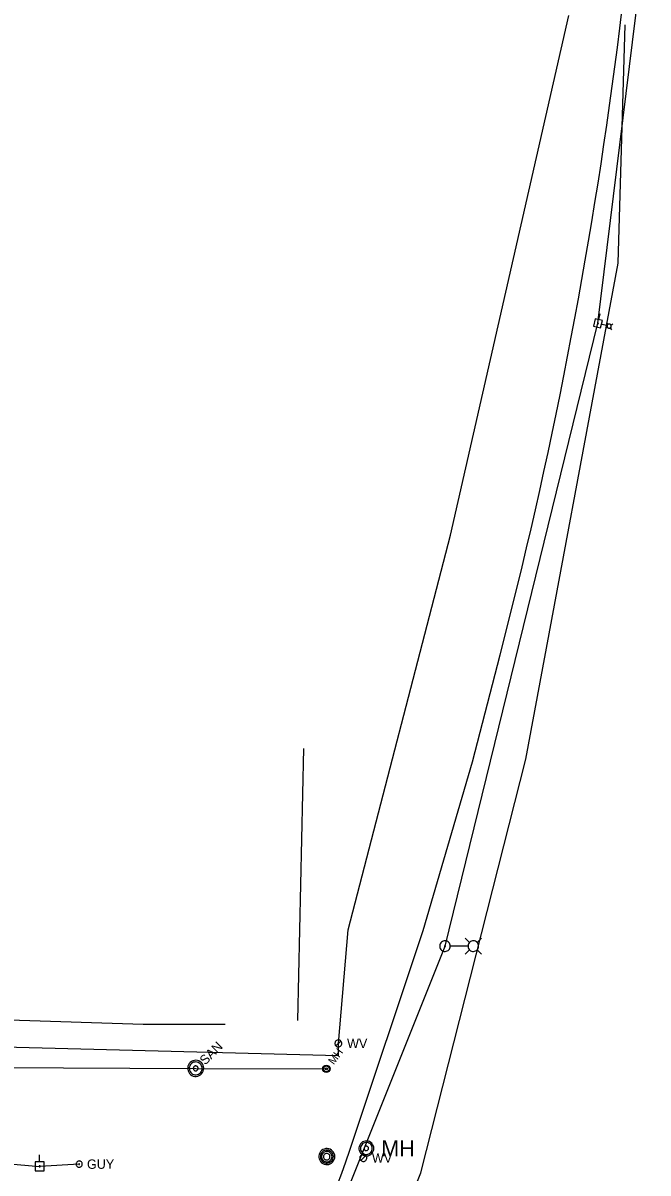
# Model space of a CAD drawing. Extents: x 600849 to 606371, y 330010 to 403088.
# Drawn here: x 604605.3 to 604861.8, y 331374.2 to 331845.6 of the extents above; entities that cross this region are included whole.
import ezdxf

# ---------------------------------------------------------------- set-up
doc = ezdxf.new("R2010")
doc.units = 0
for name, color, linetype in [('E_LTG', 7, 'Continuous'), ('E_LTG_CID', 7, 'Continuous'), ('E_UTL_EGuyWire', 7, 'Continuous'), ('E_UTL_EPowerPole', 7, 'Continuous'), ('E_UTL_G_UG', 7, 'Continuous'), ('E_UTL_MH', 7, 'Continuous'), ('E_UTL_Overhead', 7, 'Continuous'), ('E_UTL_SAN', 7, 'Continuous'), ('E_UTL_SAN_MH', 7, 'Continuous'), ('E_UTL_SAN_UG', 7, 'Continuous'), ('E_UTL_W', 7, 'Continuous'), ('E_UTL_W_MH', 7, 'Continuous'), ('E_UTL_W_UG', 7, 'Continuous')]:
    doc.layers.add(name, color=color, linetype=linetype)

msp = doc.modelspace()

# ---------------------------------------------------------------- linework, layer by layer
at = {"layer": 'E_LTG'}
for points in [[(604845.03, 331721.53), (604842.73, 331722.07)], [(604845.16, 331720.88), (604844.32, 331720.36)], [(604845.43, 331722.05), (604844.91, 331722.89)], [(604846.71, 331721.13), (604846.73, 331721.29), (604846.72, 331721.45), (604846.68, 331721.61), (604846.61, 331721.76), (604846.52, 331721.89), (604846.4, 331722), (604846.26, 331722.09), (604846.11, 331722.15), (604845.95, 331722.18), (604845.79, 331722.18), (604845.63, 331722.14), (604845.48, 331722.08), (604845.34, 331721.99), (604845.23, 331721.88), (604845.13, 331721.75), (604845.07, 331721.6), (604845.03, 331721.44), (604845.02, 331721.28), (604845.05, 331721.12), (604845.1, 331720.97), (604845.18, 331720.83), (604845.29, 331720.7), (604845.42, 331720.61), (604845.56, 331720.53), (604845.72, 331720.49), (604845.88, 331720.47), (604846.04, 331720.49), (604846.2, 331720.53), (604846.34, 331720.61), (604846.47, 331720.71), (604846.57, 331720.83), (604846.65, 331720.97), (604846.71, 331721.13)], [(604846.32, 331720.61), (604846.84, 331719.77)], [(604846.6, 331721.77), (604847.43, 331722.29)], [(604788.6, 331468.69), (604786.82, 331470.47)], [(604791.65, 331468.69), (604793.43, 331470.47)], [(604780.7, 331467.17), (604780.66, 331467.58), (604780.54, 331467.97), (604780.35, 331468.34), (604780.09, 331468.67), (604779.78, 331468.94), (604779.42, 331469.15), (604779.03, 331469.28), (604778.62, 331469.34), (604778.21, 331469.32), (604777.81, 331469.22), (604777.43, 331469.05), (604777.1, 331468.81), (604776.81, 331468.51), (604776.59, 331468.16), (604776.43, 331467.78), (604776.35, 331467.37), (604776.35, 331466.96), (604776.43, 331466.55), (604776.59, 331466.17), (604776.81, 331465.82), (604777.1, 331465.52), (604777.43, 331465.28), (604777.81, 331465.11), (604778.21, 331465.01), (604778.62, 331464.99), (604779.03, 331465.05), (604779.42, 331465.19), (604779.78, 331465.39), (604780.09, 331465.66), (604780.35, 331465.99), (604780.54, 331466.36), (604780.66, 331466.75), (604780.7, 331467.17)], [(604778.69, 331467.17), (604778.68, 331467.2), (604778.67, 331467.23), (604778.66, 331467.26), (604778.64, 331467.28), (604778.62, 331467.3), (604778.59, 331467.32), (604778.56, 331467.33), (604778.53, 331467.33), (604778.5, 331467.33), (604778.47, 331467.32), (604778.44, 331467.31), (604778.41, 331467.29), (604778.39, 331467.27), (604778.37, 331467.24), (604778.36, 331467.21), (604778.35, 331467.18), (604778.35, 331467.15), (604778.36, 331467.12), (604778.37, 331467.09), (604778.39, 331467.06), (604778.41, 331467.04), (604778.44, 331467.02), (604778.47, 331467.01), (604778.5, 331467), (604778.53, 331467), (604778.56, 331467), (604778.59, 331467.01), (604778.62, 331467.03), (604778.64, 331467.05), (604778.66, 331467.08), (604778.67, 331467.1), (604778.68, 331467.13), (604778.69, 331467.17)], [(604787.91, 331467.17), (604780.73, 331467.17)], [(604788.6, 331465.64), (604786.82, 331463.87)], [(604792.3, 331467.17), (604792.26, 331467.58), (604792.14, 331467.97), (604791.95, 331468.34), (604791.7, 331468.67), (604791.39, 331468.94), (604791.03, 331469.15), (604790.64, 331469.28), (604790.23, 331469.34), (604789.81, 331469.32), (604789.41, 331469.22), (604789.04, 331469.05), (604788.7, 331468.81), (604788.41, 331468.51), (604788.19, 331468.16), (604788.04, 331467.78), (604787.96, 331467.37), (604787.96, 331466.96), (604788.04, 331466.55), (604788.19, 331466.17), (604788.41, 331465.82), (604788.7, 331465.52), (604789.04, 331465.28), (604789.41, 331465.11), (604789.81, 331465.01), (604790.23, 331464.99), (604790.64, 331465.05), (604791.03, 331465.19), (604791.39, 331465.39), (604791.7, 331465.66), (604791.95, 331465.99), (604792.14, 331466.36), (604792.26, 331466.75), (604792.3, 331467.17)], [(604791.65, 331465.64), (604793.43, 331463.87)]]:
    msp.add_lwpolyline(points, dxfattribs=at)
at = {"layer": 'E_LTG_CID'}
msp.add_lwpolyline([(604680.92, 331223.31), (604778.52, 331467.17), (604841.28, 331722.49), (604873.72, 331985.14), (604875.05, 331997.61), (604878.05, 332072.5), (604879.01, 332133.59), (604879.29, 332193.85), (604879.03, 332249.73), (604879.6, 332255.02), (604881.21, 332520.43)], dxfattribs=at)
at = {"layer": 'E_UTL_EGuyWire'}
msp.add_line((604628.38, 331377.81), (604612.18, 331376.89), dxfattribs=at)
for points in [[(604629.67, 331377.81), (604629.64, 331378.05), (604629.57, 331378.28), (604629.46, 331378.5), (604629.31, 331378.69), (604629.13, 331378.85), (604628.92, 331378.97), (604628.69, 331379.05), (604628.44, 331379.09), (604628.2, 331379.08), (604627.96, 331379.02), (604627.74, 331378.92), (604627.54, 331378.78), (604627.37, 331378.6), (604627.24, 331378.39), (604627.15, 331378.17), (604627.11, 331377.93), (604627.11, 331377.68), (604627.15, 331377.44), (604627.24, 331377.22), (604627.37, 331377.01), (604627.54, 331376.84), (604627.74, 331376.69), (604627.96, 331376.59), (604628.2, 331376.53), (604628.44, 331376.52), (604628.69, 331376.56), (604628.92, 331376.64), (604629.13, 331376.76), (604629.31, 331376.92), (604629.46, 331377.11), (604629.57, 331377.33), (604629.64, 331377.56), (604629.67, 331377.81)], [(604628.54, 331377.81), (604628.54, 331377.84), (604628.53, 331377.86), (604628.52, 331377.89), (604628.5, 331377.92), (604628.48, 331377.94), (604628.45, 331377.95), (604628.42, 331377.96), (604628.39, 331377.97), (604628.36, 331377.96), (604628.33, 331377.96), (604628.3, 331377.94), (604628.28, 331377.93), (604628.26, 331377.9), (604628.24, 331377.88), (604628.23, 331377.85), (604628.22, 331377.82), (604628.22, 331377.79), (604628.23, 331377.76), (604628.24, 331377.73), (604628.26, 331377.71), (604628.28, 331377.68), (604628.3, 331377.67), (604628.33, 331377.65), (604628.36, 331377.65), (604628.39, 331377.65), (604628.42, 331377.65), (604628.45, 331377.66), (604628.48, 331377.67), (604628.5, 331377.69), (604628.52, 331377.72), (604628.53, 331377.75), (604628.54, 331377.77), (604628.54, 331377.81)]]:
    msp.add_lwpolyline(points, dxfattribs=at)
at = {"layer": 'E_UTL_EPowerPole'}
for points in [[(604841.61, 331723.99), (604842.17, 331726.35)], [(604840.12, 331724.35), (604839.4, 331721.35)], [(604839.4, 331721.35), (604842.39, 331720.64)], [(604843.11, 331723.64), (604840.12, 331724.35)], [(604841.47, 331722.45), (604841.48, 331722.48), (604841.48, 331722.52), (604841.47, 331722.56), (604841.45, 331722.59), (604841.43, 331722.62), (604841.4, 331722.65), (604841.37, 331722.67), (604841.34, 331722.68), (604841.3, 331722.69), (604841.26, 331722.69), (604841.22, 331722.68), (604841.19, 331722.67), (604841.16, 331722.65), (604841.13, 331722.62), (604841.11, 331722.59), (604841.09, 331722.56), (604841.08, 331722.52), (604841.08, 331722.48), (604841.09, 331722.44), (604841.1, 331722.41), (604841.12, 331722.38), (604841.14, 331722.35), (604841.17, 331722.32), (604841.21, 331722.31), (604841.24, 331722.3), (604841.28, 331722.29), (604841.32, 331722.3), (604841.36, 331722.31), (604841.39, 331722.32), (604841.42, 331722.35), (604841.44, 331722.38), (604841.46, 331722.41), (604841.47, 331722.45)], [(604842.39, 331720.64), (604843.11, 331723.64)], [(604612.15, 331378.73), (604612.15, 331381.64)], [(604614, 331378.73), (604610.31, 331378.73)], [(604610.31, 331378.73), (604610.31, 331375.04)], [(604612.42, 331376.89), (604612.42, 331376.93), (604612.41, 331376.97), (604612.38, 331377.02), (604612.36, 331377.05), (604612.32, 331377.08), (604612.28, 331377.1), (604612.24, 331377.12), (604612.2, 331377.12), (604612.15, 331377.12), (604612.11, 331377.11), (604612.06, 331377.09), (604612.03, 331377.07), (604612, 331377.03), (604611.97, 331377), (604611.96, 331376.95), (604611.95, 331376.91), (604611.95, 331376.86), (604611.96, 331376.82), (604611.97, 331376.78), (604612, 331376.74), (604612.03, 331376.71), (604612.06, 331376.68), (604612.11, 331376.66), (604612.15, 331376.65), (604612.2, 331376.65), (604612.24, 331376.65), (604612.28, 331376.67), (604612.32, 331376.69), (604612.36, 331376.72), (604612.38, 331376.76), (604612.41, 331376.8), (604612.42, 331376.84), (604612.42, 331376.89)], [(604614, 331375.04), (604614, 331378.73)], [(604610.31, 331375.04), (604614, 331375.04)]]:
    msp.add_lwpolyline(points, dxfattribs=at)
at = {"layer": 'E_UTL_G_UG'}
msp.add_lwpolyline([(604462.99, 331439.17), (604493.85, 331439.57), (604559.63, 331439.45), (604599.63, 331437), (604654.59, 331435.18), (604688.27, 331435.25)], dxfattribs=at)
at = {"layer": 'E_UTL_MH'}
for points in [[(604733.32, 331380.88), (604733.26, 331381.51), (604733.08, 331382.11), (604732.79, 331382.67), (604732.4, 331383.16), (604731.93, 331383.57), (604731.39, 331383.89), (604730.79, 331384.09), (604730.17, 331384.18), (604729.55, 331384.15), (604728.94, 331384), (604728.37, 331383.74), (604727.86, 331383.38), (604727.42, 331382.92), (604727.08, 331382.4), (604726.85, 331381.81), (604726.73, 331381.2), (604726.73, 331380.57), (604726.85, 331379.95), (604727.08, 331379.37), (604727.42, 331378.84), (604727.86, 331378.39), (604728.37, 331378.03), (604728.94, 331377.77), (604729.55, 331377.62), (604730.17, 331377.59), (604730.79, 331377.68), (604731.39, 331377.88), (604731.93, 331378.2), (604732.4, 331378.61), (604732.79, 331379.1), (604733.08, 331379.66), (604733.26, 331380.26), (604733.32, 331380.88)], [(604732.7, 331380.88), (604732.65, 331381.39), (604732.51, 331381.87), (604732.28, 331382.33), (604731.96, 331382.73), (604731.58, 331383.06), (604731.14, 331383.31), (604730.66, 331383.48), (604730.15, 331383.55), (604729.64, 331383.53), (604729.15, 331383.41), (604728.69, 331383.2), (604728.27, 331382.9), (604727.92, 331382.53), (604727.64, 331382.11), (604727.46, 331381.63), (604727.36, 331381.13), (604727.36, 331380.63), (604727.46, 331380.13), (604727.64, 331379.65), (604727.92, 331379.23), (604728.27, 331378.86), (604728.69, 331378.56), (604729.15, 331378.35), (604729.64, 331378.23), (604730.15, 331378.21), (604730.66, 331378.28), (604731.14, 331378.45), (604731.58, 331378.7), (604731.96, 331379.03), (604732.28, 331379.43), (604732.51, 331379.89), (604732.65, 331380.37), (604732.7, 331380.88)], [(604732.14, 331380.85), (604732.1, 331381.25), (604731.99, 331381.64), (604731.8, 331382), (604731.55, 331382.32), (604731.24, 331382.59), (604730.89, 331382.79), (604730.51, 331382.92), (604730.11, 331382.98), (604729.71, 331382.96), (604729.31, 331382.86), (604728.94, 331382.7), (604728.61, 331382.46), (604728.34, 331382.17), (604728.12, 331381.83), (604727.97, 331381.45), (604727.89, 331381.05), (604727.89, 331380.65), (604727.97, 331380.25), (604728.12, 331379.88), (604728.34, 331379.54), (604728.61, 331379.24), (604728.94, 331379.01), (604729.31, 331378.84), (604729.71, 331378.74), (604730.11, 331378.72), (604730.51, 331378.78), (604730.89, 331378.91), (604731.24, 331379.12), (604731.55, 331379.38), (604731.8, 331379.7), (604731.99, 331380.06), (604732.1, 331380.45), (604732.14, 331380.85)], [(604731.28, 331380.84), (604731.26, 331381.09), (604731.19, 331381.33), (604731.07, 331381.56), (604730.91, 331381.76), (604730.72, 331381.92), (604730.5, 331382.05), (604730.26, 331382.13), (604730.01, 331382.17), (604729.76, 331382.15), (604729.51, 331382.09), (604729.28, 331381.99), (604729.08, 331381.84), (604728.9, 331381.66), (604728.77, 331381.45), (604728.67, 331381.21), (604728.62, 331380.96), (604728.62, 331380.71), (604728.67, 331380.46), (604728.77, 331380.23), (604728.9, 331380.01), (604729.08, 331379.83), (604729.28, 331379.68), (604729.51, 331379.58), (604729.76, 331379.52), (604730.01, 331379.51), (604730.26, 331379.54), (604730.5, 331379.62), (604730.72, 331379.75), (604730.91, 331379.92), (604731.07, 331380.12), (604731.19, 331380.34), (604731.26, 331380.58), (604731.28, 331380.84)]]:
    msp.add_lwpolyline(points, dxfattribs=at)
at = {"layer": 'E_UTL_Overhead'}
msp.add_lwpolyline([(604364.63, 331391.63), (604461.8, 331390.13), (604612.18, 331376.89)], dxfattribs=at)
at = {"layer": 'E_UTL_SAN'}
for points in [[(604678.55, 331419.4), (604678.06, 331419.8), (604677.51, 331420.1), (604676.91, 331420.29), (604676.29, 331420.36), (604675.67, 331420.32), (604675.06, 331420.16), (604674.5, 331419.88), (604673.99, 331419.51), (604673.57, 331419.04), (604673.24, 331418.51), (604673.03, 331417.92), (604672.92, 331417.3), (604672.94, 331416.67), (604673.07, 331416.06), (604673.32, 331415.48), (604673.67, 331414.96), (604674.11, 331414.52), (604674.63, 331414.17), (604675.21, 331413.92), (604675.82, 331413.79), (604676.45, 331413.77), (604677.07, 331413.88), (604677.65, 331414.1), (604678.19, 331414.42), (604678.65, 331414.85), (604679.03, 331415.35), (604679.3, 331415.91), (604679.47, 331416.52), (604679.51, 331417.14), (604679.44, 331417.77), (604679.25, 331418.36), (604678.95, 331418.91), (604678.55, 331419.4)], [(604678.08, 331418.93), (604677.69, 331419.25), (604677.25, 331419.49), (604676.77, 331419.64), (604676.28, 331419.7), (604675.78, 331419.67), (604675.29, 331419.54), (604674.84, 331419.32), (604674.44, 331419.02), (604674.1, 331418.65), (604673.84, 331418.22), (604673.66, 331417.75), (604673.58, 331417.25), (604673.59, 331416.75), (604673.7, 331416.26), (604673.9, 331415.8), (604674.18, 331415.38), (604674.53, 331415.03), (604674.95, 331414.75), (604675.41, 331414.55), (604675.9, 331414.44), (604676.4, 331414.43), (604676.9, 331414.52), (604677.37, 331414.69), (604677.8, 331414.95), (604678.17, 331415.29), (604678.47, 331415.69), (604678.69, 331416.14), (604678.82, 331416.63), (604678.85, 331417.13), (604678.79, 331417.63), (604678.64, 331418.1), (604678.4, 331418.54), (604678.08, 331418.93)], [(604676.91, 331417.77), (604676.77, 331417.89), (604676.6, 331417.98), (604676.42, 331418.03), (604676.24, 331418.05), (604676.05, 331418.04), (604675.87, 331417.99), (604675.7, 331417.91), (604675.55, 331417.8), (604675.42, 331417.66), (604675.32, 331417.5), (604675.26, 331417.32), (604675.23, 331417.14), (604675.23, 331416.95), (604675.27, 331416.76), (604675.34, 331416.59), (604675.45, 331416.43), (604675.58, 331416.3), (604675.74, 331416.2), (604675.91, 331416.12), (604676.1, 331416.08), (604676.28, 331416.08), (604676.47, 331416.11), (604676.65, 331416.17), (604676.81, 331416.27), (604676.95, 331416.4), (604677.06, 331416.55), (604677.14, 331416.72), (604677.19, 331416.9), (604677.2, 331417.09), (604677.18, 331417.28), (604677.12, 331417.45), (604677.03, 331417.62), (604676.91, 331417.77)]]:
    msp.add_lwpolyline(points, dxfattribs=at)
at = {"layer": 'E_UTL_SAN_MH'}
for radius in [1.5, 1.2, 0.45]:
    msp.add_circle((604729.82, 331416.86), radius, dxfattribs=at)
at = {"layer": 'E_UTL_SAN_UG'}
msp.add_line((604476.65, 331417.91), (604676.22, 331417.01), dxfattribs=at)
msp.add_lwpolyline([(604676.22, 331417.01), (604729.83, 331416.85)], dxfattribs=at)
at = {"layer": 'E_UTL_W'}
for points in [[(604736.19, 331427.27), (604736.16, 331427.54), (604736.09, 331427.8), (604735.96, 331428.04), (604735.8, 331428.26), (604735.59, 331428.43), (604735.36, 331428.57), (604735.1, 331428.66), (604734.83, 331428.7), (604734.56, 331428.68), (604734.3, 331428.62), (604734.05, 331428.51), (604733.83, 331428.35), (604733.64, 331428.15), (604733.5, 331427.92), (604733.4, 331427.67), (604733.35, 331427.41), (604733.35, 331427.14), (604733.4, 331426.87), (604733.5, 331426.62), (604733.64, 331426.39), (604733.83, 331426.19), (604734.05, 331426.04), (604734.3, 331425.92), (604734.56, 331425.86), (604734.83, 331425.85), (604735.1, 331425.89), (604735.36, 331425.97), (604735.59, 331426.11), (604735.8, 331426.29), (604735.96, 331426.5), (604736.09, 331426.74), (604736.16, 331427), (604736.19, 331427.27)], [(604733.76, 331426.26), (604735.77, 331428.28)], [(604746.41, 331380.33), (604746.39, 331380.6), (604746.31, 331380.86), (604746.19, 331381.11), (604746.02, 331381.32), (604745.81, 331381.5), (604745.58, 331381.63), (604745.32, 331381.72), (604745.05, 331381.76), (604744.78, 331381.75), (604744.52, 331381.68), (604744.27, 331381.57), (604744.05, 331381.41), (604743.86, 331381.22), (604743.72, 331380.99), (604743.62, 331380.74), (604743.57, 331380.47), (604743.57, 331380.2), (604743.62, 331379.93), (604743.72, 331379.68), (604743.86, 331379.45), (604744.05, 331379.26), (604744.27, 331379.1), (604744.52, 331378.99), (604744.78, 331378.92), (604745.05, 331378.91), (604745.32, 331378.95), (604745.58, 331379.04), (604745.81, 331379.17), (604746.02, 331379.35), (604746.19, 331379.56), (604746.31, 331379.8), (604746.39, 331380.06), (604746.41, 331380.33)], [(604743.98, 331379.33), (604745.99, 331381.34)]]:
    msp.add_lwpolyline(points, dxfattribs=at)
at = {"layer": 'E_UTL_W_MH'}
for points in [[(604749.29, 331384.24), (604749.24, 331384.82), (604749.08, 331385.38), (604748.81, 331385.89), (604748.45, 331386.35), (604748.01, 331386.73), (604747.51, 331387.02), (604746.96, 331387.21), (604746.38, 331387.29), (604745.8, 331387.26), (604745.24, 331387.13), (604744.71, 331386.89), (604744.24, 331386.55), (604743.84, 331386.13), (604743.52, 331385.64), (604743.31, 331385.1), (604743.2, 331384.53), (604743.2, 331383.95), (604743.31, 331383.38), (604743.52, 331382.84), (604743.84, 331382.35), (604744.24, 331381.93), (604744.71, 331381.59), (604745.24, 331381.35), (604745.8, 331381.22), (604746.38, 331381.19), (604746.96, 331381.27), (604747.51, 331381.46), (604748.01, 331381.75), (604748.45, 331382.13), (604748.81, 331382.59), (604749.08, 331383.1), (604749.24, 331383.66), (604749.29, 331384.24)], [(604748.68, 331384.24), (604748.64, 331384.7), (604748.51, 331385.15), (604748.29, 331385.56), (604748.01, 331385.93), (604747.66, 331386.23), (604747.25, 331386.46), (604746.81, 331386.62), (604746.35, 331386.68), (604745.89, 331386.66), (604745.44, 331386.55), (604745.02, 331386.36), (604744.64, 331386.09), (604744.32, 331385.75), (604744.07, 331385.36), (604743.89, 331384.93), (604743.81, 331384.47), (604743.81, 331384.01), (604743.89, 331383.55), (604744.07, 331383.12), (604744.32, 331382.73), (604744.64, 331382.39), (604745.02, 331382.12), (604745.44, 331381.93), (604745.89, 331381.82), (604746.35, 331381.8), (604746.81, 331381.86), (604747.25, 331382.02), (604747.66, 331382.25), (604748.01, 331382.55), (604748.29, 331382.92), (604748.51, 331383.33), (604748.64, 331383.78), (604748.68, 331384.24)], [(604747.16, 331384.24), (604747.14, 331384.41), (604747.09, 331384.58), (604747.01, 331384.74), (604746.9, 331384.87), (604746.77, 331384.99), (604746.62, 331385.07), (604746.45, 331385.13), (604746.28, 331385.16), (604746.11, 331385.15), (604745.94, 331385.11), (604745.78, 331385.03), (604745.64, 331384.93), (604745.52, 331384.81), (604745.42, 331384.66), (604745.36, 331384.5), (604745.33, 331384.33), (604745.33, 331384.15), (604745.36, 331383.98), (604745.42, 331383.82), (604745.52, 331383.67), (604745.64, 331383.55), (604745.78, 331383.45), (604745.94, 331383.37), (604746.11, 331383.33), (604746.28, 331383.32), (604746.45, 331383.35), (604746.62, 331383.41), (604746.77, 331383.49), (604746.9, 331383.61), (604747.01, 331383.74), (604747.09, 331383.9), (604747.14, 331384.07), (604747.16, 331384.24)]]:
    msp.add_lwpolyline(points, dxfattribs=at)
at = {"layer": 'E_UTL_W_UG'}
for p, q in [((604718.14, 331436.66), (604720.58, 331548.2)), ((604768.62, 331374.17), (604811.69, 331543.82)), ((604768.62, 331374.17), (604811.69, 331543.82)), ((604649.65, 331083.04), (604768.62, 331374.17)), ((604768.62, 331374.17), (604768.62, 331374.17))]:
    msp.add_line(p, q, dxfattribs=at)
for points in [[(604738.76, 331473.89), (604780.74, 331635.62), (604829.31, 331848.68)], [(604811.69, 331543.82), (604849.6, 331747.14), (604852.44, 331844.91)], [(604811.69, 331543.82), (604849.6, 331747.14), (604852.44, 331844.91)], [(604739.44, 331383.52), (604769.61, 331473.63), (604789.83, 331542.72), (604801.22, 331586.62), (604808.3, 331614.89)], [(604734.76, 331427.27), (604738.76, 331473.89)], [(604459.92, 331427.24), (604507.36, 331428.16), (604734.76, 331422.27), (604734.76, 331422.27)], [(604734.76, 331422.27), (604734.76, 331427.27)]]:
    msp.add_lwpolyline(points, dxfattribs=at)
for centre, radius, start, end in [((602844.56, 332093.42), 2021.2, 346.30299, 353.58065), ((602817.06, 332055.12), 2036.32, 331.76571, 340.74254)]:
    msp.add_arc(centre, radius, start, end, dxfattribs=at)

# ---------------------------------------------------------------- texts
at = {"layer": 'E_UTL_EGuyWire'}
msp.add_text('GUY', height=3.85, dxfattribs=at).set_placement((604631.59, 331375.88))
at = {"layer": 'E_UTL_SAN'}
msp.add_text('SAN', height=3.849, rotation=45, dxfattribs=at).set_placement((604680.11, 331418.21))
at = {"layer": 'E_UTL_SAN_MH'}
msp.add_text('MH', height=3.24, rotation=53.5849, dxfattribs=at).set_placement((604732.9, 331418.31))
at = {"layer": 'E_UTL_W'}
for p in [(604738.33, 331425.35), (604748.55, 331378.41)]:
    msp.add_text('WV', height=3.85, dxfattribs=at).set_placement(p)
at = {"layer": 'E_UTL_W_MH'}
msp.add_text('MH', height=6.6, dxfattribs=at).set_placement((604752.35, 331380.94))

doc.saveas('drawing.dxf')
